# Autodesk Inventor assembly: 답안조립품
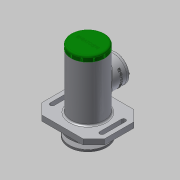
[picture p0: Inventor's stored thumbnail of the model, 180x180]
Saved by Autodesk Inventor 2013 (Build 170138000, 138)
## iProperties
Created: 2017-10
Part Number: 답안조립품
Document SubType Name: Assembly
Designer: Administrator
Author: Administrator
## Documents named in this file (20)
- C:\Users\Administrator\Desktop\471008V1009\답안조립품.iam
- C:\Users\Administrator\Desktop\471008V1009\본체.ipt
- C:\Users\Administrator\Desktop\471008V1009\V-벨트풀리.ipt
- C:\Users\Administrator\Desktop\471008V1009\너트 M10.ipt
- C:\Users\Administrator\Desktop\471008V1009\멈춤링 15 x 1.ipt
- C:\Users\Administrator\Desktop\471008V1009\멈춤링 35x1.6.ipt
- C:\Users\Administrator\Desktop\471008V1009\베어링 15 x 35 x 11.ipt
- C:\Users\Administrator\Desktop\471008V1009\볼트 M4 x 10.ipt
- C:\Users\Administrator\Desktop\471008V1009\부시1.ipt
- C:\Users\Administrator\Desktop\471008V1009\부시2.ipt
- C:\Users\Administrator\Desktop\471008V1009\사이드 커버.ipt
- 사이드 커버.ipt
- C:\Users\Administrator\Desktop\471008V1009\십자볼트 M3 x 10.ipt
- C:\Users\Administrator\Desktop\471008V1009\오일 실 15 25 7.ipt
- C:\Users\Administrator\Desktop\471008V1009\와셔 3x6.ipt
- C:\Users\Administrator\Desktop\471008V1009\와셔 4x16.ipt
- C:\Users\Administrator\Desktop\471008V1009\와셔 10x21.ipt
- C:\Users\Administrator\Desktop\471008V1009\축.ipt
- C:\Users\Administrator\Desktop\471008V1009\키 4 x 4 x 18.ipt
- C:\Users\Administrator\Desktop\471008V1009\탑 커버.ipt
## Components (2 placed, 2 different names)
1. V-벨트풀리:1
2. ISO 4017 M4 x 10:1
